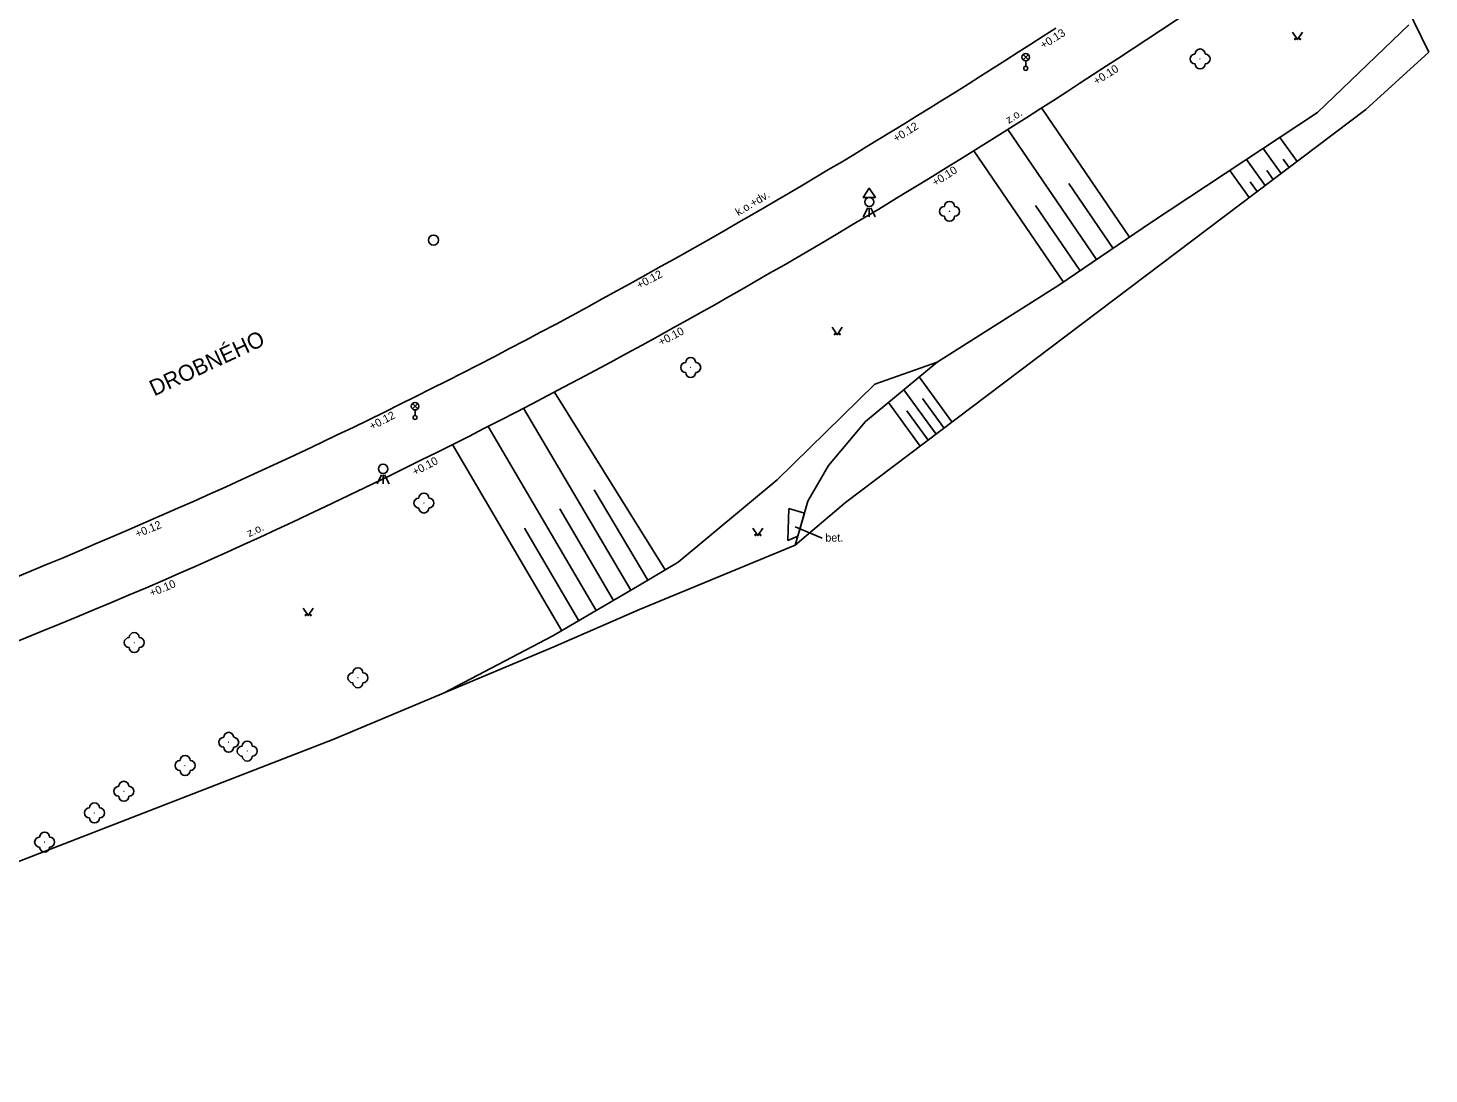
# Model space of a CAD drawing. Extents: x -597862 to -597276, y -1159156 to -1158889.
# Drawn here: x -597567.4 to -597497.4, y -1159076.4 to -1159024.1 of the extents above; entities that cross this region are included whole.
import ezdxf

# ---------------------------------------------------------------- set-up
doc = ezdxf.new("R2010")
doc.units = 0
for name, color, linetype in [('Vrstva 10', 7, 'Continuous'), ('Vrstva 14', 7, 'Continuous'), ('Vrstva 25', 7, 'Continuous'), ('Vrstva 28', 7, 'Continuous'), ('Vrstva 29', 7, 'Continuous'), ('Vrstva 41', 7, 'Continuous'), ('Vrstva 42', 7, 'Continuous'), ('Vrstva 44', 7, 'Continuous'), ('Vrstva 49', 7, 'Continuous'), ('Vrstva 50', 7, 'Continuous'), ('Vrstva 7', 7, 'Continuous')]:
    doc.layers.add(name, color=color, linetype=linetype)

msp = doc.modelspace()

# ---------------------------------------------------------------- linework, layer by layer
at = {"layer": 'Vrstva 10'}
for points in [[(-597497.377, -1159025.273), (-597500.53, -1159028.14), (-597526.553, -1159047.786)], [(-597526.553, -1159047.786), (-597529.06, -1159049.92), (-597536.843, -1159053.154), (-597541.13, -1159055.02), (-597552.14, -1159059.64), (-597569.8, -1159066.49), (-597577.13, -1159067.06), (-597595.98, -1159073.03), (-597597.07, -1159073.56), (-597604.69, -1159076.38)]]:
    msp.add_lwpolyline(points, dxfattribs=at)
at = {"layer": 'Vrstva 14'}
for points in [[(-597504.196, -1159024.265), (-597503.946, -1159024.64), (-597503.696, -1159024.265)], [(-597527.212, -1159039.026), (-597526.962, -1159039.401), (-597526.712, -1159039.026)], [(-597531.177, -1159049.07), (-597530.927, -1159049.445), (-597530.677, -1159049.07)], [(-597553.659, -1159053.079), (-597553.409, -1159053.454), (-597553.159, -1159053.079)]]:
    msp.add_lwpolyline(points, dxfattribs=at)
for centre, radius in [((-597504.071, -1159024.615), 0.025), ((-597503.821, -1159024.615), 0.025), ((-597508.82, -1159025.61), 0.00025), ((-597521.35, -1159033.23), 0.00025), ((-597527.087, -1159039.376), 0.025), ((-597526.837, -1159039.376), 0.025), ((-597534.29, -1159041.04), 0.00025), ((-597547.63, -1159047.82), 0.00025), ((-597531.052, -1159049.42), 0.025), ((-597530.802, -1159049.42), 0.025), ((-597553.534, -1159053.429), 0.025), ((-597553.284, -1159053.429), 0.025), ((-597562.11, -1159054.8), 0.00025), ((-597550.93, -1159056.56), 0.00025), ((-597557.39, -1159059.79), 0.00025), ((-597556.46, -1159060.23), 0.00025), ((-597559.57, -1159060.95), 0.00025), ((-597562.63, -1159062.24), 0.00025), ((-597564.1, -1159063.32), 0.00025), ((-597566.59, -1159064.78), 0.00025)]:
    msp.add_circle(centre, radius, dxfattribs=at)
for centre, start, end in [((-597508.82, -1159025.36), 0, 179.99999), ((-597509.07, -1159025.61), 89.99999, 269.99999), ((-597508.82, -1159025.86), 179.99999, 359.99999), ((-597508.57, -1159025.61), 270, 89.99999), ((-597521.35, -1159032.98), 0, 179.99999), ((-597521.6, -1159033.23), 89.99999, 269.99999), ((-597521.35, -1159033.48), 179.99999, 359.99999), ((-597521.1, -1159033.23), 270, 89.99999), ((-597534.29, -1159040.79), 0, 179.99999), ((-597534.54, -1159041.04), 89.99999, 269.99999), ((-597534.29, -1159041.29), 179.99999, 359.99999), ((-597534.04, -1159041.04), 270, 89.99999), ((-597547.88, -1159047.82), 89.99999, 269.99999), ((-597547.63, -1159047.57), 0, 179.99999), ((-597547.38, -1159047.82), 270, 89.99999), ((-597547.63, -1159048.07), 179.99999, 359.99999), ((-597562.36, -1159054.8), 89.99999, 269.99999), ((-597562.11, -1159054.55), 0, 179.99999), ((-597561.86, -1159054.8), 270, 89.99999), ((-597562.11, -1159055.05), 179.99999, 359.99999), ((-597550.93, -1159056.31), 0, 179.99999), ((-597551.18, -1159056.56), 89.99999, 269.99999), ((-597550.68, -1159056.56), 270, 89.99999), ((-597550.93, -1159056.81), 179.99999, 359.99999), ((-597557.64, -1159059.79), 89.99999, 269.99999), ((-597557.39, -1159059.54), 0, 179.99999), ((-597557.14, -1159059.79), 270, 89.99999), ((-597557.39, -1159060.04), 179.99999, 359.99999), ((-597556.71, -1159060.23), 89.99999, 269.99999), ((-597556.46, -1159059.98), 0, 179.99999), ((-597556.21, -1159060.23), 270, 89.99999), ((-597559.82, -1159060.95), 89.99999, 269.99999), ((-597559.57, -1159060.7), 0, 179.99999), ((-597559.32, -1159060.95), 270, 89.99999), ((-597556.46, -1159060.48), 179.99999, 359.99999), ((-597559.57, -1159061.2), 179.99999, 359.99999), ((-597562.88, -1159062.24), 89.99999, 269.99999), ((-597562.63, -1159061.99), 0, 179.99999), ((-597562.38, -1159062.24), 270, 89.99999), ((-597564.35, -1159063.32), 89.99999, 269.99999), ((-597564.1, -1159063.07), 0, 179.99999), ((-597563.85, -1159063.32), 270, 89.99999), ((-597562.63, -1159062.49), 179.99999, 359.99999), ((-597564.1, -1159063.57), 179.99999, 359.99999), ((-597566.59, -1159064.53), 0, 179.99999), ((-597566.84, -1159064.78), 89.99999, 269.99999), ((-597566.59, -1159065.03), 179.99999, 359.99999), ((-597566.34, -1159064.78), 270, 89.99999)]:
    msp.add_arc(centre, 0.25, start, end, dxfattribs=at)
at = {"layer": 'Vrstva 25'}
msp.add_circle((-597547.15, -1159034.67), 0.25, dxfattribs=at)
at = {"layer": 'Vrstva 28'}
for p, q in [((-597512.346, -1159034.518), (-597516.753, -1159028.061)), ((-597513.998, -1159035.646), (-597518.441, -1159029.135)), ((-597504.769, -1159031.34), (-597505.668, -1159030.084)), ((-597503.971, -1159030.738), (-597504.833, -1159029.533)), ((-597515.65, -1159036.773), (-597520.138, -1159030.198)), ((-597505.567, -1159031.943), (-597506.503, -1159030.636)), ((-597504.37, -1159031.039), (-597504.665, -1159030.627)), ((-597506.366, -1159032.546), (-597507.338, -1159031.187)), ((-597505.168, -1159031.642), (-597505.489, -1159031.194)), ((-597515.385, -1159031.84), (-597513.172, -1159035.082)), ((-597505.966, -1159032.244), (-597506.313, -1159031.76)), ((-597517.056, -1159032.939), (-597514.824, -1159036.209)), ((-597521.227, -1159043.765), (-597522.865, -1159041.512)), ((-597535.568, -1159051.166), (-597541.102, -1159042.27)), ((-597522.025, -1159044.368), (-597523.636, -1159042.152)), ((-597521.627, -1159044.067), (-597522.695, -1159042.596)), ((-597537.288, -1159052.187), (-597542.651, -1159043.08)), ((-597522.824, -1159044.97), (-597524.407, -1159042.792)), ((-597522.425, -1159044.67), (-597523.485, -1159043.21)), ((-597539.013, -1159053.199), (-597544.415, -1159043.99)), ((-597540.738, -1159054.211), (-597546.203, -1159044.894)), ((-597539.11, -1159047.157), (-597536.427, -1159051.678)), ((-597540.838, -1159048.112), (-597538.151, -1159052.693)), ((-597542.592, -1159049.075), (-597539.876, -1159053.705))]:
    msp.add_line(p, q, dxfattribs=at)
at = {"layer": 'Vrstva 29'}
for p, q in [((-597517.672, -1159025.649), (-597517.408, -1159025.385)), ((-597517.404, -1159025.648), (-597517.668, -1159025.383)), ((-597517.54, -1159025.98), (-597517.54, -1159025.705)), ((-597548.202, -1159043.109), (-597547.938, -1159042.845)), ((-597547.934, -1159043.108), (-597548.198, -1159042.843)), ((-597548.07, -1159043.44), (-597548.07, -1159043.165))]:
    msp.add_line(p, q, dxfattribs=at)
for centre, radius in [((-597517.54, -1159025.518), 0.188), ((-597517.54, -1159026.08), 0.1), ((-597548.07, -1159042.978), 0.188), ((-597548.07, -1159043.54), 0.1)]:
    msp.add_circle(centre, radius, dxfattribs=at)
at = {"layer": 'Vrstva 41'}
for points in [[(-597498.39, -1159023.9), (-597502.95, -1159028.29), (-597511.25, -1159033.77), (-597515.88, -1159036.93), (-597521.97, -1159040.77), (-597525.55, -1159043.74), (-597527.4, -1159045.94), (-597528.43, -1159047.72), (-597529.06, -1159049.92)], [(-597521.97, -1159040.77), (-597525.08, -1159041.88), (-597529.96, -1159046.66), (-597534.92, -1159050.78), (-597536.843, -1159051.926), (-597541.18, -1159054.47), (-597546.65, -1159057.336)]]:
    msp.add_lwpolyline(points, dxfattribs=at)
at = {"layer": 'Vrstva 44'}
for p, q in [((-597525.435, -1159033.06), (-597525.66, -1159033.51)), ((-597525.36, -1159033.06), (-597525.36, -1159033.51)), ((-597525.285, -1159033.06), (-597525.06, -1159033.51)), ((-597549.744, -1159046.403), (-597549.97, -1159046.855)), ((-597549.67, -1159046.405), (-597549.67, -1159046.855)), ((-597549.595, -1159046.403), (-597549.37, -1159046.855))]:
    msp.add_line(p, q, dxfattribs=at)
msp.add_lwpolyline([(-597525.057, -1159032.536), (-597525.659, -1159032.536), (-597525.36, -1159032.079)], close=True, dxfattribs=at)
for centre, radius in [((-597525.36, -1159032.76), 0.224), ((-597549.67, -1159046.11), 0.234)]:
    msp.add_circle(centre, radius, dxfattribs=at)
at = {"layer": 'Vrstva 49'}
msp.add_line((-597529.068, -1159049.018), (-597527.722, -1159049.583), dxfattribs=at)
at = {"layer": 'Vrstva 7'}
for p, q in [((-597529.38, -1159048.1), (-597529.425, -1159049.693)), ((-597529.425, -1159049.693), (-597528.935, -1159049.484))]:
    msp.add_line(p, q, dxfattribs=at)
for points in [[(-597506.91, -1159009.15), (-597501.11, -1159017.61), (-597497.377, -1159025.273)], [(-597529.38, -1159048.1), (-597528.603, -1159048.323), (-597528.935, -1159049.484)]]:
    msp.add_lwpolyline(points, dxfattribs=at)
for centre, radius, start, end in [((-597737.715, -1158680.771), 411.616, 303.00547, 304.96212), ((-597700.567, -1158741.003), 337.893, 299.06654, 303.10058), ((-597705.907, -1158732.284), 351.093, 299.09969, 303.23153), ((-597670.457, -1158797.242), 274.11, 293.41475, 299.27659), ((-597682.649, -1158773.488), 303.778, 293.67026, 299.04616), ((-597681.397, -1158774.818), 299.037, 288.10461, 293.63083), ((-597696.607, -1158735.145), 344.509, 288.30583, 293.23618)]:
    msp.add_arc(centre, radius, start, end, dxfattribs=at)

# ---------------------------------------------------------------- texts
at = {"layer": 'Vrstva 42'}
msp.add_text('DROBNÉHO', height=0.8, rotation=24.93016, dxfattribs=at).set_placement((-597561.115, -1159042.492))
at = {"layer": 'Vrstva 49'}
for s, rotation, p in [('z.o.', 32.4483, (-597518.39, -1159028.864)), ('k.o.+dv.', 31.14813, (-597531.908, -1159033.477)), ('z.o.', 24.98968, (-597556.367, -1159049.53))]:
    msp.add_text(s, height=0.4, rotation=rotation, dxfattribs=at).set_placement(p)
msp.add_text('bet.', height=0.4, dxfattribs=at).set_placement((-597527.556, -1159049.751))
at = {"layer": 'Vrstva 50'}
for s, rotation, p in [('+0.13', 32.33494, (-597516.659, -1159025.128)), ('+0.10', 32.33494, (-597513.998, -1159026.926)), ('+0.12', 32.33494, (-597524.012, -1159029.797)), ('+0.10', 32.33494, (-597522.066, -1159031.997)), ('+0.12', 27.71218, (-597536.865, -1159037.13)), ('+0.10', 27.71218, (-597535.779, -1159039.975)), ('+0.12', 27.71218, (-597550.225, -1159044.187)), ('+0.10', 27.71218, (-597548.08, -1159046.467)), ('+0.12', 22.28683, (-597561.965, -1159049.568)), ('+0.10', 22.28683, (-597561.25, -1159052.52))]:
    msp.add_text(s, height=0.4, rotation=rotation, dxfattribs=at).set_placement(p)

doc.saveas('drawing.dxf')
